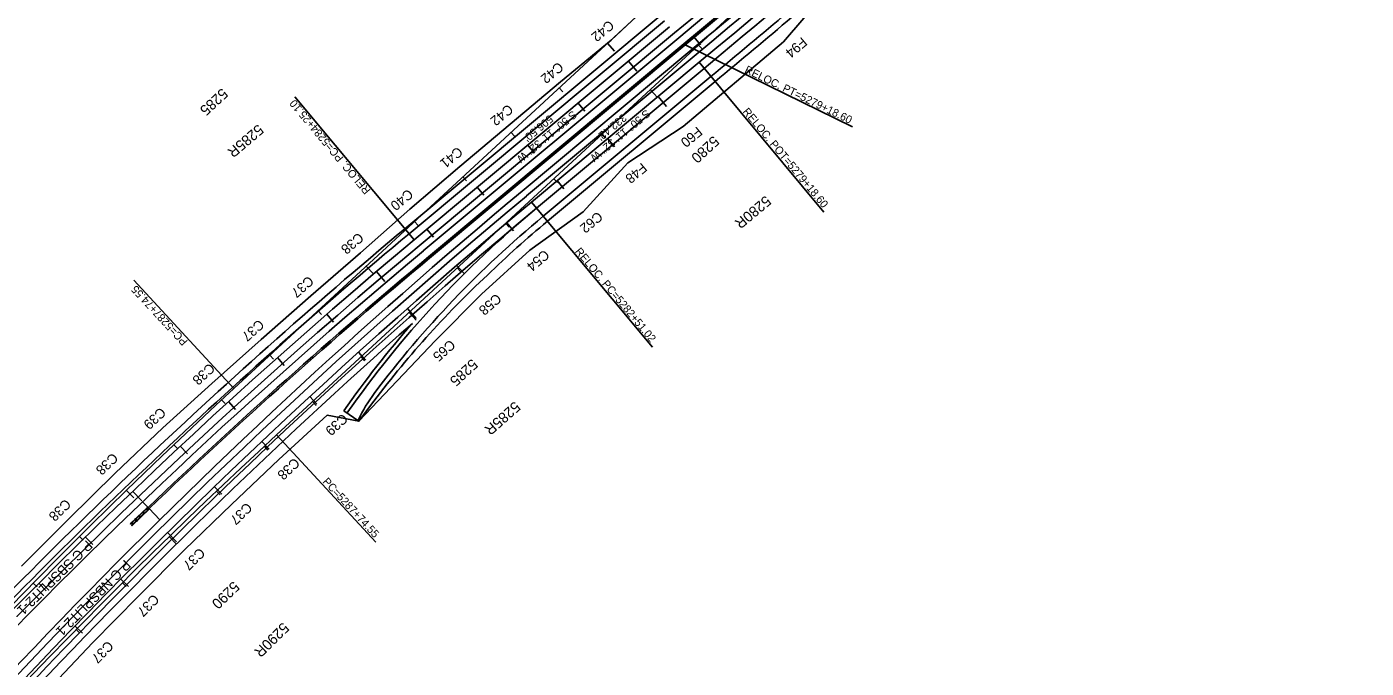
# Model space of a CAD drawing. Extents: x 2160877 to 2175861, y 601747 to 617724.
# Drawn here: x 2163357 to 2165397, y 605468 to 606444 of the extents above; entities that cross this region are included whole.
import ezdxf

# ---------------------------------------------------------------- set-up
doc = ezdxf.new("R2010")
doc.units = 0
for name, color, linetype in [('RD_HC_Cl', 7, 'Continuous'), ('RD_HC_CL_Rel', 7, 'Continuous'), ('RD_HC_Data', 7, 'Continuous'), ('RD_HC_Data_Rel', 7, 'Continuous'), ('RD_HC_Data_Tic', 7, 'Continuous'), ('RD_HC_Data_Tic_Rel', 7, 'Continuous'), ('RD_HC_TX_Rel_Sta50', 7, 'Continuous'), ('RD_HC_TX_Rel_StaOther', 7, 'Continuous'), ('RD_HC_TX_StaOther', 7, 'Continuous'), ('RD_PD_CstnLmt', 7, 'Continuous'), ('RD_PD_CstnLmt_TX', 7, 'Continuous'), ('RD_PD_Final_LnLine', 7, 'Continuous'), ('RD_PD_Final_TrvlWay', 7, 'Continuous'), ('RD_PD_GR', 7, 'Continuous')]:
    doc.layers.add(name, color=color, linetype=linetype)

msp = doc.modelspace()

# ---------------------------------------------------------------- linework, layer by layer
at = {"layer": 'RD_HC_Cl'}
for p, q in [((2172207.3, 613775.1), (2163672.2, 605893.8)), ((2172272.5, 613704.6), (2163737.4, 605823.3))]:
    msp.add_line(p, q, dxfattribs=at)
for radius in [8641.9, 8545.9]:
    msp.add_arc((2169535, 599544.7), radius, 132.71947, 164.41949, dxfattribs=at)
at = {"layer": 'RD_HC_CL_Rel'}
for p, q in [((2164335.8, 606444.4), (2163946.7, 606120.1)), ((2164380.9, 606390.4), (2164125.5, 606177.5))]:
    msp.add_line(p, q, dxfattribs=at)
for centre, radius, start, end in [((2135996.9, 640448.5), 44300, 309.80773, 312.71947), ((2169810, 599356.6), 8879.1, 129.80773, 145.62858), ((2169305.2, 599690.4), 8369.8, 129.80773, 147.62243)]:
    msp.add_arc(centre, radius, start, end, dxfattribs=at)
at = {"layer": 'RD_HC_Data'}
for p, q in [((2163672.2, 605893.8), (2163520.1, 606058.6)), ((2163737.4, 605823.3), (2163888.4, 605659.7))]:
    msp.add_line(p, q, dxfattribs=at)
at = {"layer": 'RD_HC_Data_Rel'}
for p, q in [((2164358.3, 606417.4), (2164614.3, 606291.9)), ((2164380.9, 606390.4), (2164570.9, 606162.4)), ((2163946.7, 606120.1), (2163765.3, 606337.8)), ((2164125.5, 606177.5), (2164309.7, 605956.5))]:
    msp.add_line(p, q, dxfattribs=at)
at = {"layer": 'RD_HC_Data_Tic'}
for p, q in [((2164241.3, 606419.3), (2164252.1, 606407.5)), ((2164379.9, 606416.6), (2164385.3, 606410.7)), ((2164167.8, 606351.4), (2164173.3, 606345.6)), ((2164306.4, 606348.8), (2164317.3, 606337)), ((2164094.4, 606283.6), (2164099.8, 606277.7)), ((2164233, 606280.9), (2164238.4, 606275)), ((2164020.9, 606215.8), (2164026.3, 606209.9)), ((2164159.5, 606213.1), (2164164.9, 606207.2)), ((2163947.4, 606147.9), (2163952.8, 606142)), ((2164086, 606145.2), (2164091.4, 606139.4)), ((2163873.9, 606080.1), (2163884.8, 606068.3)), ((2164012.5, 606077.4), (2164018, 606071.5)), ((2163800.5, 606012.2), (2163805.9, 606006.4)), ((2163939.1, 606009.5), (2163949.9, 605997.8)), ((2163727, 605944.4), (2163732.4, 605938.5)), ((2163865.6, 605941.7), (2163871, 605935.8)), ((2163653.6, 605876.5), (2163659, 605870.7)), ((2163792.1, 605873.9), (2163797.6, 605868)), ((2163580.7, 605808), (2163586.2, 605802.3)), ((2163718.7, 605806), (2163724.1, 605800.1)), ((2163508.6, 605738.7), (2163519.8, 605727.3)), ((2163645.8, 605737.5), (2163651.3, 605731.7)), ((2163437.4, 605668.6), (2163443, 605662.9)), ((2163573.8, 605668.2), (2163584.9, 605656.7)), ((2163366.9, 605597.6), (2163372.6, 605592)), ((2163502.5, 605598), (2163508.2, 605592.3)), ((2163432.1, 605527), (2163437.8, 605521.4))]:
    msp.add_line(p, q, dxfattribs=at)
at = {"layer": 'RD_HC_Data_Tic_Rel'}
for p, q in [((2164372.6, 606429.3), (2164382.9, 606417)), ((2164273.3, 606392.3), (2164286.1, 606376.9)), ((2164196.5, 606328.3), (2164206.7, 606316)), ((2164318.3, 606338.2), (2164331.1, 606322.9)), ((2164119.7, 606264.2), (2164129.9, 606251.9)), ((2164241.5, 606274.2), (2164251.7, 606261.9)), ((2164042.8, 606200.2), (2164053.1, 606187.9)), ((2164164.7, 606210.2), (2164174.9, 606197.9)), ((2164087.9, 606146.1), (2164098.3, 606133.8)), ((2163966, 606136.2), (2163976.3, 606123.9)), ((2164011.8, 606081.2), (2164022.3, 606069.1)), ((2163889.4, 606071.9), (2163902.4, 606056.7)), ((2163813.6, 606006.8), (2163824.1, 605994.7)), ((2163936.5, 606015.5), (2163949.7, 606000.5)), ((2163738.5, 605940.7), (2163749.1, 605928.7)), ((2163861.9, 605948.9), (2163872.6, 605937)), ((2163664.2, 605873.7), (2163675, 605861.9)), ((2163788, 605881.5), (2163798.8, 605869.7)), ((2163714.9, 605813.3), (2163725.9, 605801.6)), ((2163590.7, 605805.9), (2163601.7, 605794.2)), ((2163518.1, 605737.2), (2163531.9, 605722.7)), ((2163642.6, 605744.2), (2163653.7, 605732.7)), ((2163571, 605674.4), (2163585.1, 605660.1)), ((2163446.2, 605667.6), (2163457.4, 605656.2)), ((2163375.3, 605597.2), (2163386.6, 605585.9)), ((2163500.3, 605603.7), (2163511.6, 605592.4)), ((2163430.3, 605532.2), (2163441.8, 605521.1))]:
    msp.add_line(p, q, dxfattribs=at)
at = {"layer": 'RD_PD_CstnLmt'}
for p, q in [((2164392.9, 606560.8), (2164246.7, 606424.2)), ((2164575.6, 606498.7), (2164509.5, 606421.7)), ((2164246.7, 606424.2), (2164169.6, 606360.5)), ((2164509.5, 606421.7), (2164356.5, 606292.4)), ((2164169.6, 606360.5), (2164093, 606296.2)), ((2164418.9, 606344.8), (2164418.9, 606344.8)), ((2164093, 606296.2), (2164016.5, 606231.8)), ((2164356.5, 606292.4), (2164272.2, 606237.3)), ((2164016.5, 606231.8), (2163940.4, 606166.9)), ((2164272.2, 606237.3), (2164204.3, 606162.7)), ((2163940.4, 606166.9), (2163865.1, 606100.5)), ((2164204.3, 606162.7), (2164123, 606104.5)), ((2163865.1, 606100.5), (2163789.3, 606034.7)), ((2164123, 606104.5), (2164049.6, 606037.4)), ((2164049.6, 606037.4), (2163979.3, 605966.9)), ((2163789.3, 606034.7), (2163713.9, 605968.3)), ((2163713.9, 605968.3), (2163638.9, 605901.5)), ((2163979.3, 605966.9), (2163862.6, 605843.8)), ((2163638.9, 605901.5), (2163564.3, 605834.1)), ((2163814.2, 605853.1), (2163741, 605785.6)), ((2163862.6, 605843.8), (2163814.2, 605853.1)), ((2163564.3, 605834.1), (2163491.7, 605764.8)), ((2163741, 605785.6), (2163668.5, 605717.3)), ((2163491.7, 605764.8), (2163419.9, 605694.5)), ((2163668.5, 605717.3), (2163596.9, 605648.2)), ((2163419.9, 605694.5), (2163348.9, 605623.5)), ((2163596.9, 605648.2), (2163526.8, 605577.4)), ((2163526.8, 605577.4), (2163457.1, 605506.3)), ((2163457.1, 605506.3), (2163388.7, 605434))]:
    msp.add_line(p, q, dxfattribs=at)
at = {"layer": 'RD_PD_Final_LnLine'}
for p, q in [((2163939.1, 606129.3), (2164328.1, 606453.6)), ((2163954.4, 606110.9), (2164343.5, 606435.2)), ((2163968.5, 606094), (2164357.6, 606418.3)), ((2163970, 606092.2), (2164359.1, 606416.5)), ((2164117.8, 606186.8), (2164373.2, 606399.6)), ((2164388.5, 606381.1), (2164133.2, 606168.3)), ((2164398.8, 606368.9), (2164143.4, 606156)), ((2163862.6, 605843.8), (2163839.6, 605859.9)), ((2163861.2, 605844.7), (2163861.9, 605846.1)), ((2163543.1, 605711), (2163533.3, 605721.3)), ((2163543.1, 605711), (2163559.5, 605693.9))]:
    msp.add_line(p, q, dxfattribs=at)
for centre, radius, start, end in [((2135996.9, 640448.5), 44276.8, 309.80773, 312.71947), ((2135996.9, 640448.5), 44298.8, 309.80773, 312.71947), ((2135996.9, 640448.5), 44301.2, 309.80773, 312.71947), ((2135996.9, 640448.5), 44323.2, 309.80773, 312.71947), ((2135996.9, 640448.5), 44335.2, 309.80773, 312.71947), ((2135996.9, 640448.5), 44347.2, 309.80773, 310.84704), ((2135996.9, 640448.5), 44363.2, 309.80773, 310.20085), ((2169810, 599356.6), 8891.1, 129.80773, 145.62858), ((2169810, 599356.6), 8867.1, 129.80773, 144.89859), ((2165149.7, 604937.9), 1596, 129.5633, 144.8644), ((2165161.7, 604927.1), 1596, 129.6453, 143.0585), ((2169305.2, 599690.4), 8381.8, 129.80773, 136.90521), ((2169305.2, 599690.4), 8357.8, 129.80773, 147.62243), ((2169327, 599664.3), 8369.8, 129.80773, 133.72726), ((2169327, 599664.3), 8367.5, 129.80773, 133.72726), ((2164070.6, 605747.6), 230.8, 143.0585, 154.736)]:
    msp.add_arc(centre, radius, start, end, dxfattribs=at)
at = {"layer": 'RD_PD_Final_TrvlWay'}
for p, q in [((2163932.7, 606137), (2164321.7, 606461.3)), ((2163960.8, 606103.2), (2164349.9, 606427.5)), ((2164111.4, 606194.4), (2164366.8, 606407.3)), ((2164405.2, 606361.2), (2164149.8, 606148.4)), ((2163862.6, 605843.8), (2163880.5, 605867.8))]:
    msp.add_line(p, q, dxfattribs=at)
for centre, radius, start, end in [((2135996.9, 640448.5), 44286.8, 309.80773, 311.17861), ((2135996.9, 640448.5), 44313.2, 309.80773, 311.17861), ((2135996.9, 640448.5), 44373.2, 309.80773, 310.2011), ((2169810, 599356.6), 8901.1, 129.80773, 142.13894), ((2165161.7, 604927.1), 1586, 129.6453, 134.0776), ((2169305.2, 599690.4), 8391.8, 129.80773, 137.30123), ((2169305.2, 599690.4), 8347.8, 129.80773, 143.57306), ((2165082.4, 604970.4), 1500, 133.0506, 143.2516), ((2169810, 599356.6), 8857.1, 131.47407, 142.45996), ((2165149.7, 604937.9), 1602, 138.8128, 144.8644)]:
    msp.add_arc(centre, radius, start, end, dxfattribs=at)
at = {"layer": 'RD_PD_GR'}
for p, q in [((2163541.1, 605713.2), (2163514.4, 605687.5)), ((2163541.1, 605713.2), (2163514.4, 605687.5)), ((2163514.7, 605687.2), (2163541.4, 605712.8)), ((2163514.7, 605687.2), (2163541.4, 605712.8)), ((2163516.6, 605685.2), (2163543.3, 605710.9)), ((2163516.6, 605685.2), (2163543.3, 605710.9)), ((2163543.6, 605710.5), (2163516.9, 605684.9)), ((2163543.6, 605710.5), (2163516.9, 605684.9)), ((2163538.5, 605710.8), (2163539.7, 605712)), ((2163538.5, 605710.8), (2163539.7, 605712)), ((2163538.9, 605710.4), (2163540.1, 605711.6)), ((2163538.9, 605710.4), (2163540.1, 605711.6)), ((2163540.3, 605708.9), (2163538.9, 605710.4)), ((2163540.3, 605708.9), (2163538.9, 605710.4)), ((2163540, 605710.5), (2163539.1, 605711.4)), ((2163540, 605710.5), (2163539.1, 605711.4)), ((2163540.6, 605711.1), (2163539.3, 605709.9)), ((2163540.6, 605711.1), (2163539.3, 605709.9)), ((2163540.1, 605711.6), (2163541.5, 605710.1)), ((2163540.1, 605711.6), (2163541.5, 605710.1)), ((2163541.5, 605710.1), (2163540.3, 605708.9)), ((2163541.5, 605710.1), (2163540.3, 605708.9)), ((2163542, 605709.7), (2163540.6, 605711.1)), ((2163542, 605709.7), (2163540.6, 605711.1)), ((2163541.4, 605712.8), (2163541.1, 605713.2)), ((2163541.4, 605712.8), (2163541.1, 605713.2)), ((2163543.3, 605710.9), (2163543.6, 605710.5)), ((2163543.3, 605710.9), (2163543.6, 605710.5)), ((2163515.4, 605688.6), (2163516.7, 605689.8)), ((2163515.4, 605688.6), (2163516.7, 605689.8)), ((2163519.3, 605691.6), (2163519, 605691.9)), ((2163519.3, 605691.6), (2163519, 605691.9)), ((2163521.2, 605694.2), (2163522.4, 605695.4)), ((2163521.2, 605694.2), (2163522.4, 605695.4)), ((2163521.2, 605689.6), (2163521.5, 605689.3)), ((2163521.2, 605689.6), (2163521.5, 605689.3)), ((2163521.6, 605693.7), (2163522.8, 605694.9)), ((2163521.6, 605693.7), (2163522.8, 605694.9)), ((2163523, 605692.3), (2163521.6, 605693.7)), ((2163523, 605692.3), (2163521.6, 605693.7)), ((2163522.7, 605693.9), (2163521.8, 605694.8)), ((2163522.7, 605693.9), (2163521.8, 605694.8)), ((2163523.3, 605694.5), (2163522, 605693.3)), ((2163523.3, 605694.5), (2163522, 605693.3)), ((2163522, 605693.3), (2163523.4, 605691.8)), ((2163522, 605693.3), (2163523.4, 605691.8)), ((2163522.8, 605694.9), (2163524.2, 605693.5)), ((2163522.8, 605694.9), (2163524.2, 605693.5)), ((2163524.2, 605693.5), (2163523, 605692.3)), ((2163524.2, 605693.5), (2163523, 605692.3)), ((2163524.7, 605693), (2163523.3, 605694.5)), ((2163524.7, 605693), (2163523.3, 605694.5)), ((2163523.4, 605691.8), (2163524.7, 605693)), ((2163523.4, 605691.8), (2163524.7, 605693)), ((2163523.6, 605692.9), (2163524.5, 605692)), ((2163523.6, 605692.9), (2163524.5, 605692)), ((2163523.8, 605691.4), (2163525.1, 605692.6)), ((2163523.8, 605691.4), (2163525.1, 605692.6)), ((2163526.9, 605699.7), (2163528.2, 605700.9)), ((2163526.9, 605699.7), (2163528.2, 605700.9)), ((2163527.3, 605699.3), (2163528.6, 605700.5)), ((2163527.3, 605699.3), (2163528.6, 605700.5)), ((2163528.7, 605697.8), (2163527.3, 605699.3)), ((2163528.7, 605697.8), (2163527.3, 605699.3)), ((2163528.4, 605699.4), (2163527.6, 605700.3)), ((2163528.4, 605699.4), (2163527.6, 605700.3)), ((2163529.1, 605700), (2163527.8, 605698.8)), ((2163529.1, 605700), (2163527.8, 605698.8)), ((2163527.8, 605698.8), (2163529.2, 605697.4)), ((2163527.8, 605698.8), (2163529.2, 605697.4)), ((2163528.6, 605700.5), (2163530, 605699.1)), ((2163528.6, 605700.5), (2163530, 605699.1)), ((2163530, 605699.1), (2163528.7, 605697.8)), ((2163530, 605699.1), (2163528.7, 605697.8)), ((2163530.5, 605698.6), (2163529.1, 605700)), ((2163530.5, 605698.6), (2163529.1, 605700)), ((2163529.2, 605697.4), (2163530.5, 605698.6)), ((2163529.2, 605697.4), (2163530.5, 605698.6)), ((2163529.4, 605698.4), (2163530.2, 605697.5)), ((2163529.4, 605698.4), (2163530.2, 605697.5)), ((2163529.6, 605696.9), (2163530.9, 605698.2)), ((2163529.6, 605696.9), (2163530.9, 605698.2)), ((2163532.7, 605705.2), (2163534, 605706.5)), ((2163532.7, 605705.2), (2163534, 605706.5)), ((2163533.1, 605704.8), (2163534.4, 605706)), ((2163533.1, 605704.8), (2163534.4, 605706)), ((2163534.5, 605703.4), (2163533.1, 605704.8)), ((2163534.5, 605703.4), (2163533.1, 605704.8)), ((2163534.2, 605705), (2163533.3, 605705.9)), ((2163534.2, 605705), (2163533.3, 605705.9)), ((2163534.8, 605705.6), (2163533.6, 605704.3)), ((2163534.8, 605705.6), (2163533.6, 605704.3)), ((2163533.6, 605704.3), (2163535, 605702.9)), ((2163533.6, 605704.3), (2163535, 605702.9)), ((2163534.4, 605706), (2163535.8, 605704.6)), ((2163534.4, 605706), (2163535.8, 605704.6)), ((2163535.8, 605704.6), (2163534.5, 605703.4)), ((2163535.8, 605704.6), (2163534.5, 605703.4)), ((2163536.2, 605704.1), (2163534.8, 605705.6)), ((2163536.2, 605704.1), (2163534.8, 605705.6)), ((2163535, 605702.9), (2163536.2, 605704.1)), ((2163535, 605702.9), (2163536.2, 605704.1)), ((2163535.1, 605704), (2163536, 605703.1)), ((2163535.1, 605704), (2163536, 605703.1)), ((2163535.4, 605702.5), (2163536.6, 605703.7)), ((2163535.4, 605702.5), (2163536.6, 605703.7)), ((2163539.3, 605709.9), (2163540.7, 605708.5)), ((2163539.3, 605709.9), (2163540.7, 605708.5)), ((2163540.7, 605708.5), (2163542, 605709.7)), ((2163540.7, 605708.5), (2163542, 605709.7)), ((2163540.9, 605709.5), (2163541.8, 605708.6)), ((2163540.9, 605709.5), (2163541.8, 605708.6)), ((2163541.1, 605708), (2163542.4, 605709.2)), ((2163541.1, 605708), (2163542.4, 605709.2)), ((2163514.4, 605687.5), (2163514.7, 605687.2)), ((2163514.4, 605687.5), (2163514.7, 605687.2)), ((2163515.8, 605688.2), (2163517.1, 605689.4)), ((2163515.8, 605688.2), (2163517.1, 605689.4)), ((2163517.2, 605686.7), (2163515.8, 605688.2)), ((2163517.2, 605686.7), (2163515.8, 605688.2)), ((2163516.9, 605688.3), (2163516, 605689.2)), ((2163516.9, 605688.3), (2163516, 605689.2)), ((2163517.5, 605688.9), (2163516.3, 605687.7)), ((2163517.5, 605688.9), (2163516.3, 605687.7)), ((2163516.3, 605687.7), (2163517.7, 605686.3)), ((2163516.3, 605687.7), (2163517.7, 605686.3)), ((2163516.9, 605684.9), (2163516.6, 605685.2)), ((2163516.9, 605684.9), (2163516.6, 605685.2)), ((2163517.1, 605689.4), (2163518.5, 605688)), ((2163517.1, 605689.4), (2163518.5, 605688)), ((2163518.5, 605688), (2163517.2, 605686.7)), ((2163518.5, 605688), (2163517.2, 605686.7)), ((2163518.9, 605687.5), (2163517.5, 605688.9)), ((2163518.9, 605687.5), (2163517.5, 605688.9)), ((2163517.7, 605686.3), (2163518.9, 605687.5)), ((2163517.7, 605686.3), (2163518.9, 605687.5)), ((2163517.8, 605687.4), (2163518.7, 605686.5)), ((2163517.8, 605687.4), (2163518.7, 605686.5)), ((2163518.1, 605685.8), (2163519.3, 605687.1)), ((2163518.1, 605685.8), (2163519.3, 605687.1))]:
    msp.add_line(p, q, dxfattribs=at)

# ---------------------------------------------------------------- texts
at = {"layer": 'RD_HC_Data'}
for rotation, p in [(132.7195, (2163602.9, 605965.9)), (312.7195, (2163806.7, 605751.2))]:
    msp.add_text('PC=5287+74.55', height=12, rotation=rotation, dxfattribs=at).set_placement(p)
at = {"layer": 'RD_HC_Data_Rel'}
for s, height, rotation, p in [('RELOC. PT=5279+18.60', 12, 333.8917, (2164449, 606375.2)), ('RELOC. PC=5284+25.10', 12, 129.8077, (2163881.2, 606195.7)), ('RELOC. POT=5279+18.60', 12, 309.8077, (2164446.4, 606314.8)), ('RELOC. PC=5282+51.02', 12, 309.8077, (2164191, 606102)), ('P C SBSPLIT2-1', 15, 224.5304, (2163448.1, 605663.6)), ('P C NBSPLIT2-1', 15, 225.4895, (2163506.1, 605633.9))]:
    msp.add_text(s, height=height, rotation=rotation, dxfattribs=at).set_placement(p)
at = {"layer": 'RD_HC_TX_Rel_Sta50'}
for s, rotation, p in [('5285R', 220.3205, (2163709.1, 606296.9)), ('5280R', 219.8077, (2164482, 606188.3)), ('5285R', 221.4144, (2164099.8, 605875.1)), ('5290R', 224.6408, (2163746.8, 605538.7))]:
    msp.add_text(s, height=16, rotation=rotation, dxfattribs=at).set_placement(p)
at = {"layer": 'RD_HC_TX_Rel_StaOther'}
for s, p in [('S 50%%d 11\' 32" W', (2164188.2, 606317.5)), ("506.50'", (2164152.3, 606311)), ('S 50%%d 11\' 32" W', (2164300.1, 606319.2)), ("332.42'", (2164264.2, 606312.7))]:
    msp.add_text(s, height=12, rotation=219.8077, dxfattribs=at).set_placement(p)
at = {"layer": 'RD_HC_TX_StaOther'}
for s, rotation, p in [('5285', 222.7195, (2163654.1, 606351.9)), ('5280', 222.7195, (2164402.3, 606279.4)), ('5285', 222.7195, (2164034.6, 605939.8)), ('5290', 224.231, (2163671.4, 605601.3))]:
    msp.add_text(s, height=16, rotation=rotation, dxfattribs=at).set_placement(p)
at = {"layer": 'RD_PD_CstnLmt_TX'}
for s, rotation, p in [('C42', 219.8077, (2164243.5, 606455.5)), ('F94', 219.9611, (2164537.3, 606429.6)), ('C42', 219.8077, (2164166.4, 606391.8)), ('C42', 219.8077, (2164089.8, 606327.5)), ('F60', 219.8077, (2164377.8, 606293.3)), ('C41', 219.8077, (2164013, 606262.8)), ('F48', 219.8077, (2164293.5, 606238.2)), ('C40', 219.8077, (2163937.5, 606198.4)), ('C62', 219.8077, (2164226.2, 606164.1)), ('C38', 220.3205, (2163862, 606132.1)), ('C54', 220.1238, (2164144.9, 606106)), ('C37', 221.005, (2163785.8, 606066.2)), ('C58', 220.7691, (2164071.7, 606039.3)), ('C37', 221.6896, (2163710.2, 605999.9)), ('C65', 221.4144, (2164001.4, 605969.1)), ('C38', 222.3741, (2163635, 605933.4)), ('C39', 223.0587, (2163560.2, 605866.1)), ('C39', 222.705, (2163837.3, 605856.6)), ('C38', 223.7432, (2163487.3, 605796.8)), ('C38', 223.3502, (2163764, 605789.3)), ('C38', 224.4278, (2163415.3, 605726.6)), ('C37', 223.9955, (2163691.4, 605721.2)), ('C37', 224.6408, (2163619.6, 605652.3)), ('C37', 225.2861, (2163549.5, 605581.7)), ('C37', 225.9314, (2163479.8, 605510.8))]:
    msp.add_text(s, height=15, rotation=rotation, dxfattribs=at).set_placement(p)

doc.saveas('drawing.dxf')
